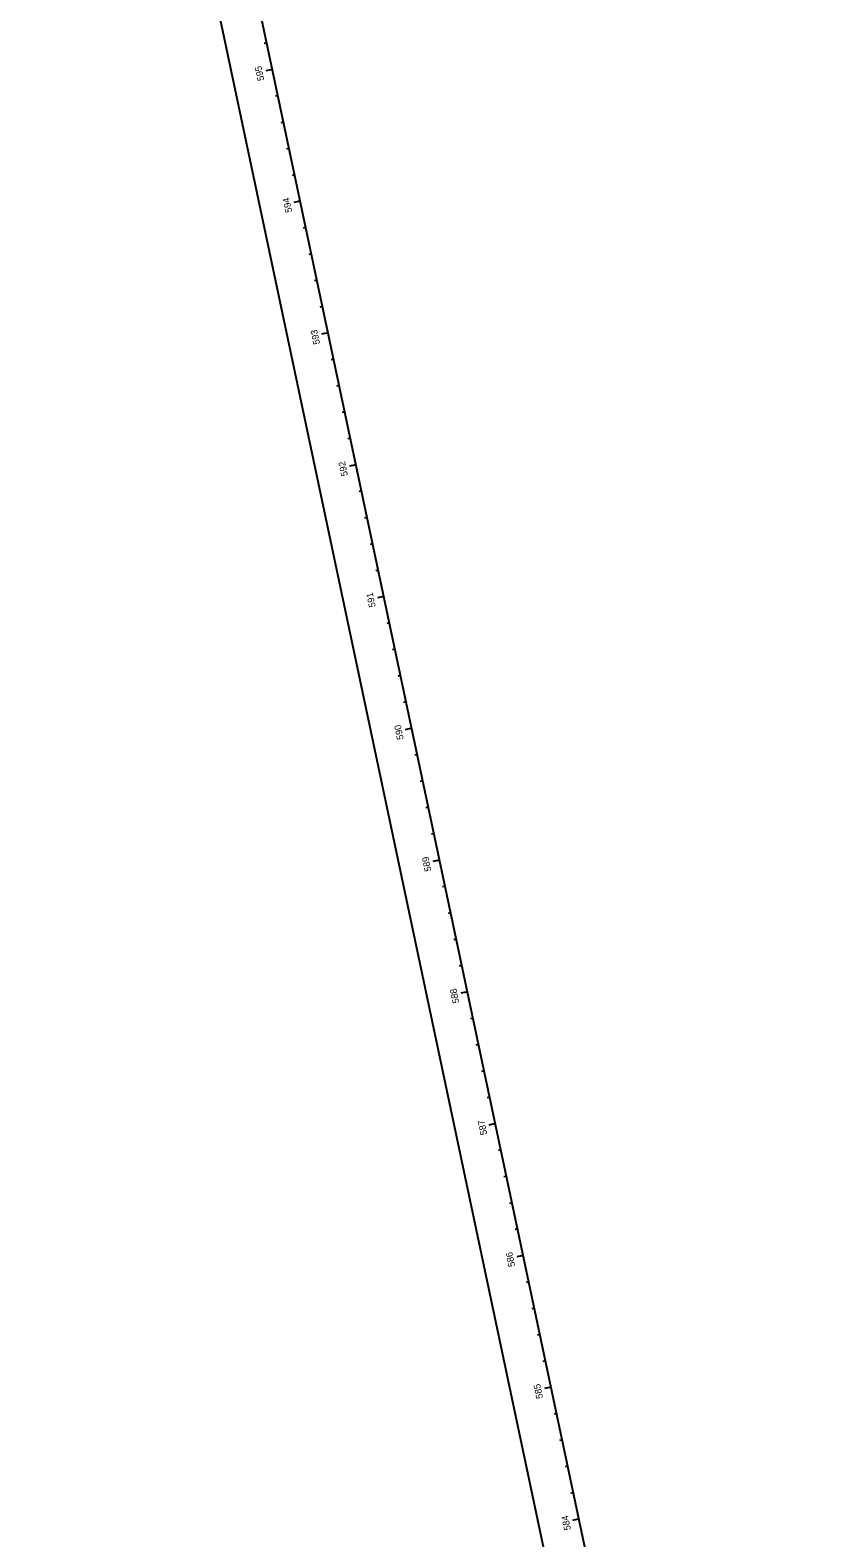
# Model space of a CAD drawing. Extents: x 2003883 to 2007688, y 399149 to 412300.
# Drawn here: x 2005065 to 2005645, y 405714 to 406834 of the extents above; entities that cross this region are included whole.
import ezdxf

# ---------------------------------------------------------------- set-up
doc = ezdxf.new("R2010")
doc.units = 0
for name, color, linetype in [('BaselineSurvey', 7, 'Continuous'), ('DataBoxWt2', 7, 'Continuous'), ('Default', 7, 'Continuous'), ('EaseLine_ep', 7, 'Continuous'), ('PropertyLine_ep', 7, 'Continuous'), ('PropertyLineHook_ep', 7, 'Continuous'), ('PropertyLineSymbol_ep', 7, 'Continuous'), ('SubDivLineText', 7, 'Continuous'), ('SubLotNumberText', 7, 'Continuous'), ('SubVacOrigLotStaTie', 7, 'Continuous')]:
    doc.layers.add(name, color=color, linetype=linetype)

msp = doc.modelspace()

# ---------------------------------------------------------------- linework, layer by layer
at = {"layer": 'DataBoxWt2'}
for p, q in [((2005265.6, 406706.7), (2005263.6, 406706.3)), ((2005307, 406511), (2005305, 406510.6)), ((2005348.3, 406315.4), (2005343.5, 406314.3)), ((2005389.7, 406119.7), (2005387.8, 406119.3)), ((2005431.1, 405924), (2005429.1, 405923.6)), ((2005472.5, 405728.4), (2005470.5, 405727.9))]:
    msp.add_line(p, q, dxfattribs=at)
at = {"layer": 'Default'}
msp.add_line((2006223.9, 402174.4), (2005094.5, 407516), dxfattribs=at)
at = {"layer": 'EaseLine_ep'}
msp.add_line((2006194.6, 402168.2), (2005065.1, 407509.8), dxfattribs=at)
at = {"layer": 'PropertyLine_ep'}
msp.add_line((2006223.9, 402174.4), (2005094.5, 407516), dxfattribs=at)
at = {"layer": 'PropertyLineHook_ep'}
for p, q in [((2005240.8, 406824.1), (2005238.8, 406823.7)), ((2005244.9, 406804.6), (2005240, 406803.5)), ((2005249.1, 406785), (2005247.1, 406784.6)), ((2005253.2, 406765.4), (2005251.2, 406765)), ((2005257.3, 406745.9), (2005255.4, 406745.4)), ((2005261.5, 406726.3), (2005259.5, 406725.9)), ((2005265.6, 406706.7), (2005260.7, 406705.7)), ((2005269.7, 406687.2), (2005267.8, 406686.7)), ((2005273.9, 406667.6), (2005271.9, 406667.2)), ((2005278, 406648), (2005276.1, 406647.6)), ((2005282.2, 406628.5), (2005280.2, 406628)), ((2005286.3, 406608.9), (2005281.4, 406607.9)), ((2005290.4, 406589.3), (2005288.5, 406588.9)), ((2005294.6, 406569.8), (2005292.6, 406569.3)), ((2005298.7, 406550.2), (2005296.7, 406549.8)), ((2005302.8, 406530.6), (2005300.9, 406530.2)), ((2005307, 406511), (2005302.1, 406510)), ((2005311.1, 406491.5), (2005309.2, 406491.1)), ((2005315.3, 406471.9), (2005313.3, 406471.5)), ((2005319.4, 406452.3), (2005317.4, 406451.9)), ((2005323.5, 406432.8), (2005321.6, 406432.4)), ((2005327.7, 406413.2), (2005322.8, 406412.2)), ((2005331.8, 406393.6), (2005329.8, 406393.2)), ((2005335.9, 406374.1), (2005334, 406373.7)), ((2005340.1, 406354.5), (2005338.1, 406354.1)), ((2005344.2, 406334.9), (2005342.3, 406334.5)), ((2005348.3, 406315.4), (2005343.5, 406314.3)), ((2005352.5, 406295.8), (2005350.5, 406295.4)), ((2005356.6, 406276.2), (2005354.7, 406275.8)), ((2005360.8, 406256.7), (2005358.8, 406256.3)), ((2005364.9, 406237.1), (2005362.9, 406236.7)), ((2005369, 406217.5), (2005364.1, 406216.5)), ((2005373.2, 406198), (2005371.2, 406197.6)), ((2005377.3, 406178.4), (2005375.4, 406178)), ((2005381.4, 406158.8), (2005379.5, 406158.4)), ((2005385.6, 406139.3), (2005383.6, 406138.9)), ((2005389.7, 406119.7), (2005384.8, 406118.7)), ((2005393.9, 406100.1), (2005391.9, 406099.7)), ((2005398, 406080.6), (2005396, 406080.2)), ((2005402.1, 406061), (2005400.2, 406060.6)), ((2005406.3, 406041.4), (2005404.3, 406041)), ((2005410.4, 406021.9), (2005405.5, 406020.8)), ((2005414.5, 406002.3), (2005412.6, 406001.9)), ((2005418.7, 405982.7), (2005416.7, 405982.3)), ((2005422.8, 405963.2), (2005420.9, 405962.7)), ((2005427, 405943.6), (2005425, 405943.2)), ((2005431.1, 405924), (2005426.2, 405923)), ((2005435.2, 405904.5), (2005433.3, 405904)), ((2005439.4, 405884.9), (2005437.4, 405884.5)), ((2005443.5, 405865.3), (2005441.6, 405864.9)), ((2005447.6, 405845.8), (2005445.7, 405845.3)), ((2005451.8, 405826.2), (2005446.9, 405825.2)), ((2005455.9, 405806.6), (2005454, 405806.2)), ((2005460.1, 405787.1), (2005458.1, 405786.6)), ((2005464.2, 405767.5), (2005462.2, 405767.1)), ((2005468.3, 405747.9), (2005466.4, 405747.5)), ((2005472.5, 405728.4), (2005467.6, 405727.3))]:
    msp.add_line(p, q, dxfattribs=at)
at = {"layer": 'SubDivLineText'}
for p, q in [((2005244.9, 406804.6), (2005240, 406803.5)), ((2005265.6, 406706.7), (2005263.6, 406706.3)), ((2005286.3, 406608.9), (2005284.3, 406608.5)), ((2005307, 406511), (2005305, 406510.6)), ((2005327.7, 406413.2), (2005325.7, 406412.8)), ((2005348.3, 406315.4), (2005343.5, 406314.3)), ((2005369, 406217.5), (2005367.1, 406217.1)), ((2005389.7, 406119.7), (2005387.8, 406119.3)), ((2005410.4, 406021.9), (2005408.5, 406021.5)), ((2005431.1, 405924), (2005429.1, 405923.6)), ((2005451.8, 405826.2), (2005446.9, 405825.2)), ((2005472.5, 405728.4), (2005470.5, 405727.9))]:
    msp.add_line(p, q, dxfattribs=at)
at = {"layer": 'SubVacOrigLotStaTie'}
msp.add_line((2005348.3, 406315.4), (2005346.4, 406315), dxfattribs=at)

# ---------------------------------------------------------------- texts
at = {"layer": 'BaselineSurvey'}
msp.add_text('590', height=4.98, rotation=101.9388, dxfattribs=at).set_placement((2005342.4, 406307.5))
at = {"layer": 'PropertyLineSymbol_ep'}
for s, p in [('595', (2005238.9, 406796.6)), ('594', (2005259.6, 406698.8)), ('593', (2005280.3, 406600.9)), ('592', (2005301, 406503.1)), ('591', (2005321.6, 406405.7)), ('590', (2005342.4, 406307.5)), ('589', (2005363, 406209.6)), ('588', (2005383.7, 406111.7)), ('587', (2005404.4, 406014)), ('586', (2005425.1, 405916.1)), ('585', (2005445.8, 405818.2)), ('584', (2005466.5, 405720.5))]:
    msp.add_text(s, height=4.98, rotation=101.9388, dxfattribs=at).set_placement(p)
at = {"layer": 'SubLotNumberText'}
for s, p in [('595', (2005238.9, 406796.6)), ('590', (2005342.4, 406307.5)), ('585', (2005445.8, 405818.2))]:
    msp.add_text(s, height=4.98, rotation=101.9388, dxfattribs=at).set_placement(p)

doc.saveas('drawing.dxf')
